(* Logix 5000 project; controller DNP3Master vendor 1 type 14 code 96 rev 19.13; software revision 19.01 *)

TASK DNP3ReportByException (periodic, rate 20 ms, priority 10, watchdog 500 ms) : DNP3Events
TASK MainTask (continuous, watchdog 500 ms) : MainProgram

MODULES
   Local : vendor 1 type 14 code 96 (ICP 0, rev 19.13)
      eth : vendor 1 type 12 code 200 (Ethernet 192.168.1.129, ICP 1, rev 5.7)
         PLX51DNP : ETHERNET-MODULE (Ethernet 192.168.1.231, rev 1.1, Output RPI 10 ms)
END_MODULES

TYPE PLX51DNPInput :
STRUCT
   Instance : STRING;
   Status : PLX51DNPStatus;
   MasterMappedStatus : BOOL[1024];
   TransactionRate : DINT;
   Temperature : REAL;
   DNP3RxPacketCount : DINT;
   DNP3TxPacketCount : DINT;
   DNP3ChecksumErrors : DINT;
   DNP3MsgTimeout : DINT;
   AuthenticationFailures : DINT;
   SessionKeyChanges : DINT;
   TagReads : DINT;
   TagWrites : DINT;
   TagConnectionFailures : DINT;
   TagErrors : DINT;
   MasterEventBufferIndex : DINT;
END_STRUCT
END_TYPE

TYPE PLX51DNPOutput :
STRUCT
   RoutingInhibited : BOOL;
END_STRUCT
END_TYPE

TYPE PLX51DNPStatus :
STRUCT
   ReactiveTagMode : BOOL;
   ScheduledTagMode : BOOL;
   UnscheduledMode : BOOL;
   ConfigurationValid : BOOL;
   RoutingInhibited : BOOL;
   DNP3EventLogOk : BOOL;
   DNP3EventLogOverflow : BOOL;
END_STRUCT
END_TYPE

TYPE PSDNP3AnalogInput16Flag :
STRUCT
   Online : BOOL;
   Restart : BOOL;
   CommLost : BOOL;
   RemoteForced : BOOL;
   LocalForced : BOOL;
   OverRange : BOOL;
   ReferenceError : BOOL;
   Value : INT;
END_STRUCT
END_TYPE

TYPE PSDNP3AnalogInput32Flag :
STRUCT
   Online : BOOL;
   Restart : BOOL;
   CommLost : BOOL;
   RemoteForced : BOOL;
   LocalForced : BOOL;
   OverRange : BOOL;
   ReferenceError : BOOL;
   Value : DINT;
END_STRUCT
END_TYPE

TYPE PSDNP3AnalogInputRealFlag :
STRUCT
   Online : BOOL;
   Restart : BOOL;
   CommLost : BOOL;
   RemoteForced : BOOL;
   LocalForced : BOOL;
   OverRange : BOOL;
   ReferenceError : BOOL;
   Value : REAL;
END_STRUCT
END_TYPE

TYPE PSDNP3AnalogInputVar0 :
STRUCT
   Online : BOOL;
   Restart : BOOL;
   CommLost : BOOL;
   RemoteForced : BOOL;
   LocalForced : BOOL;
   OverRange : BOOL;
   ReferenceError : BOOL;
   IntValue : DINT;
   FloatValue : REAL;
END_STRUCT
END_TYPE

TYPE PSDNP3AnalogOutput16 :
STRUCT
   RequestPending : BOOL;
   Reserved : INT;
   Value : INT;
   Status : SINT;
END_STRUCT
END_TYPE

TYPE PSDNP3AnalogOutput32 :
STRUCT
   RequestPending : BOOL;
   Reserved : INT;
   Value : DINT;
   Status : SINT;
END_STRUCT
END_TYPE

TYPE PSDNP3AnalogOutputReal :
STRUCT
   RequestPending : BOOL;
   Reserved : INT;
   Value : REAL;
   Status : SINT;
END_STRUCT
END_TYPE

TYPE PSDNP3AnalogOutputStatus16Flag :
STRUCT
   Online : BOOL;
   Restart : BOOL;
   CommLost : BOOL;
   RemoteForced : BOOL;
   LocalForced : BOOL;
   OverRange : BOOL;
   ReferenceError : BOOL;
   Value : INT;
END_STRUCT
END_TYPE

TYPE PSDNP3AnalogOutputStatus32Flag :
STRUCT
   Online : BOOL;
   Restart : BOOL;
   CommLost : BOOL;
   RemoteForced : BOOL;
   LocalForced : BOOL;
   OverRange : BOOL;
   ReferenceError : BOOL;
   Value : DINT;
END_STRUCT
END_TYPE

TYPE PSDNP3AnalogOutputStatusRealFlag :
STRUCT
   Online : BOOL;
   Restart : BOOL;
   CommLost : BOOL;
   RemoteForced : BOOL;
   LocalForced : BOOL;
   OverRange : BOOL;
   ReferenceError : BOOL;
   Value : REAL;
END_STRUCT
END_TYPE

TYPE PSDNP3AnalogOutputVar0 :
STRUCT
   Online : BOOL;
   Restart : BOOL;
   CommLost : BOOL;
   RemoteForced : BOOL;
   LocalForced : BOOL;
   OverRange : BOOL;
   ReferenceError : BOOL;
   IntValue : DINT;
   FloatValue : REAL;
END_STRUCT
END_TYPE

TYPE PSDNP3BinaryInputPacked :
STRUCT
   BinaryValues : SINT[32];
END_STRUCT
END_TYPE

TYPE PSDNP3BinaryInputWithFlag :
STRUCT
   Online : BOOL;
   Restart : BOOL;
   CommLost : BOOL;
   RemoteForced : BOOL;
   LocalForced : BOOL;
   ChatterFilter : BOOL;
   Reserved : BOOL;
   State : BOOL;
END_STRUCT
END_TYPE

TYPE PSDNP3BinaryOutputPacked :
STRUCT
   BinaryValues : SINT[32];
END_STRUCT
END_TYPE

TYPE PSDNP3BinaryOutputPulse :
STRUCT
   Count : SINT;
   OnTimer : TIMER;
   OffTimer : TIMER;
END_STRUCT
END_TYPE

TYPE PSDNP3BinaryOutputWithFlag :
STRUCT
   Online : BOOL;
   Restart : BOOL;
   CommLost : BOOL;
   RemoteForced : BOOL;
   LocalForced : BOOL;
   Reserved1 : BOOL;
   Reserved2 : BOOL;
   State : BOOL;
END_STRUCT
END_TYPE

TYPE PSDNP3Counter16WithFlag :
STRUCT
   Online : BOOL;
   Restart : BOOL;
   CommLost : BOOL;
   RemoteForced : BOOL;
   LocalForced : BOOL;
   RollOver : BOOL;
   Discontinuity : BOOL;
   Value : INT;
END_STRUCT
END_TYPE

TYPE PSDNP3Counter32WithFlag :
STRUCT
   Online : BOOL;
   Restart : BOOL;
   CommLost : BOOL;
   RemoteForced : BOOL;
   LocalForced : BOOL;
   RollOver : BOOL;
   Discontinuity : BOOL;
   Value : DINT;
END_STRUCT
END_TYPE

TYPE PSDNP3CROB :
STRUCT
   RequestPending : BOOL;
   Reserved : INT;
   ControlCode : SINT;
   Count : SINT;
   OnTime : DINT;
   OffTime : DINT;
   StatusCode : SINT;
END_STRUCT
END_TYPE

TYPE PSDNP3DoubleBinaryInputPacked :
STRUCT
   BinaryValues : SINT[32];
END_STRUCT
END_TYPE

TYPE PSDNP3DoubleBinaryInputWithFlag :
STRUCT
   Online : BOOL;
   Restart : BOOL;
   CommLost : BOOL;
   RemoteForced : BOOL;
   LocalForced : BOOL;
   ChatterFilter : BOOL;
   State0 : BOOL;
   State1 : BOOL;
END_STRUCT
END_TYPE

TYPE PSDNP3FreezeCmd :
STRUCT
   RequestPending : BOOL;
END_STRUCT
END_TYPE

TYPE PSDNP3FrozenAnalog16WithFlag :
STRUCT
   Online : BOOL;
   Restart : BOOL;
   CommLost : BOOL;
   RemoteForced : BOOL;
   LocalForced : BOOL;
   OverRange : BOOL;
   ReferenceErr : BOOL;
   Value : INT;
END_STRUCT
END_TYPE

TYPE PSDNP3FrozenAnalog16WithFlagTime :
STRUCT
   Online : BOOL;
   Restart : BOOL;
   CommLost : BOOL;
   RemoteForced : BOOL;
   LocalForced : BOOL;
   OverRange : BOOL;
   ReferenceErr : BOOL;
   Value : INT;
   Reserved : DINT;
   TimeOfOccurrence : LINT;
END_STRUCT
END_TYPE

TYPE PSDNP3FrozenAnalog32WithFlag :
STRUCT
   Online : BOOL;
   Restart : BOOL;
   CommLost : BOOL;
   RemoteForced : BOOL;
   LocalForced : BOOL;
   OverRange : BOOL;
   ReferenceErr : BOOL;
   Value : DINT;
END_STRUCT
END_TYPE

TYPE PSDNP3FrozenAnalog32WithFlagTime :
STRUCT
   Online : BOOL;
   Restart : BOOL;
   CommLost : BOOL;
   RemoteForced : BOOL;
   LocalForced : BOOL;
   OverRange : BOOL;
   ReferenceErr : BOOL;
   Value : DINT;
   TimeOfOccurrence : LINT;
END_STRUCT
END_TYPE

TYPE PSDNP3FrozenAnalogRealWithFlag :
STRUCT
   Online : BOOL;
   Restart : BOOL;
   CommLost : BOOL;
   RemoteForced : BOOL;
   LocalForced : BOOL;
   OverRange : BOOL;
   ReferenceErr : BOOL;
   Value : REAL;
END_STRUCT
END_TYPE

TYPE PSDNP3FrozenCounter16WithFlag :
STRUCT
   Online : BOOL;
   Restart : BOOL;
   CommLost : BOOL;
   RemoteForced : BOOL;
   LocalForced : BOOL;
   RollOver : BOOL;
   Discontinuity : BOOL;
   Value : INT;
END_STRUCT
END_TYPE

TYPE PSDNP3FrozenCounter16WithFlagTime :
STRUCT
   Online : BOOL;
   Restart : BOOL;
   CommLost : BOOL;
   RemoteForced : BOOL;
   LocalForced : BOOL;
   RollOver : BOOL;
   Discontinuity : BOOL;
   Value : INT;
   TimeOfOccurrence : LINT;
END_STRUCT
END_TYPE

TYPE PSDNP3FrozenCounter32WithFlag :
STRUCT
   Online : BOOL;
   Restart : BOOL;
   CommLost : BOOL;
   RemoteForced : BOOL;
   LocalForced : BOOL;
   RollOver : BOOL;
   Discontinuity : BOOL;
   Value : DINT;
END_STRUCT
END_TYPE

TYPE PSDNP3FrozenCounter32WithFlagTime :
STRUCT
   Online : BOOL;
   Restart : BOOL;
   CommLost : BOOL;
   RemoteForced : BOOL;
   LocalForced : BOOL;
   RollOver : BOOL;
   Discontinuity : BOOL;
   Value : DINT;
   TimeOfOccurrence : LINT;
END_STRUCT
END_TYPE

TYPE PSDNP3MasterEvent :
STRUCT
   EvtPending : DINT;
   EvtGroup : SINT;
   EvtFlags : SINT;
   EvtSrcNodeAddress : INT;
   EvtSrcIPAddress : INT[4];
   EvtElementIndex : DINT;
   Reserved : DINT;
   EvtTimeStamp : LINT;
   EvtFloatValue : REAL;
   EvtIntegerValue : DINT;
END_STRUCT
END_TYPE

TYPE PSDNP3MsgRequest :
STRUCT
   DestinationNode : INT;
   RequestDataSize : INT;
   IPAddress : INT[4];
   Function : DINT;
   RequestData : SINT[255];
END_STRUCT
END_TYPE

TYPE PSDNP3MsgResponse :
STRUCT
   DNP3Indicators : INT;
   ResponseDataSize : INT;
   ResponseData : SINT[255];
END_STRUCT
END_TYPE

ADD_ON_INSTRUCTION PSDNP3EventG01V02   (* revision 1.0, vendor ProSoft Technology Inc *)
// Processes DNP3 Event and updates corresponding static DNP3 object. (Report by Exception.)
// G01V02 - Binary Input - with Status
VAR_IN_OUT
   EventBuffer : PSDNP3MasterEvent[1]; {required}
END_VAR
VAR_INPUT
   BufferSize : DINT; {required}
   CurrentBufferIndex : DINT; {required}
   Reset : BOOL; {required}
   OutstationNodeAddress : INT; {required}
   OutstationIPAddress0 : INT; {required}
   OutstationIPAddress1 : INT; {required}
   OutstationIPAddress2 : INT; {required}
   OutstationIPAddress3 : INT; {required}
END_VAR
VAR_IN_OUT
   DNP3StaticObject : PSDNP3BinaryInputWithFlag[1]; {required}
END_VAR
VAR_INPUT
   MaxtElementCount : DINT; {required}
END_VAR
VAR_OUTPUT
   EventsProcessed : DINT; {access Read Only, visible}
   LastElementIndex : DINT; {access Read Only, visible}
   LastValue : BOOL; {access Read Only, visible}
   LastStatus : SINT; {access Read Only, visible}
   CurrentUnloadIndex : DINT; {access Read Only, visible}
END_VAR
VAR
   UnloadIndex : DINT; {access None}
   EnableInTemp : BOOL; {access None}
   InitialScan : BOOL; {access None}
   EntryValidForProcessing : BOOL; {access None}
   ElementIndex : DINT; {access None}
   NextIndex : DINT; {access None}
   ResetPulse : BOOL; {access None}
   ResetONS : BOOL; {access None}
END_VAR

ROUTINE Logic   (* ladder *)
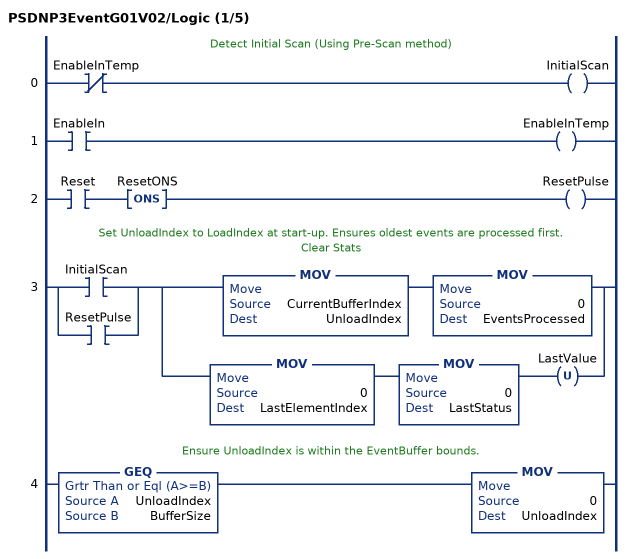
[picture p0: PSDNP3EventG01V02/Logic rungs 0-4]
   // Detect Initial Scan (Using Pre-Scan method)
   0: XIO(EnableInTemp)OTE(InitialScan);
   1: XIC(EnableIn)OTE(EnableInTemp);
   2: XIC(Reset)ONS(ResetONS)OTE(ResetPulse);
   // Set UnloadIndex to LoadIndex at start-up. Ensures oldest events are processed first.
   // Clear Stats
   3: [XIC(InitialScan) ,XIC(ResetPulse) ][MOV(CurrentBufferIndex,UnloadIndex) MOV(0,EventsProcessed) ,MOV(0,LastElementIndex) MOV(0,LastStatus) OTU(LastValue) ];
   // Ensure UnloadIndex is within the EventBuffer bounds.
   4: GEQ(UnloadIndex,BufferSize)MOV(0,UnloadIndex);
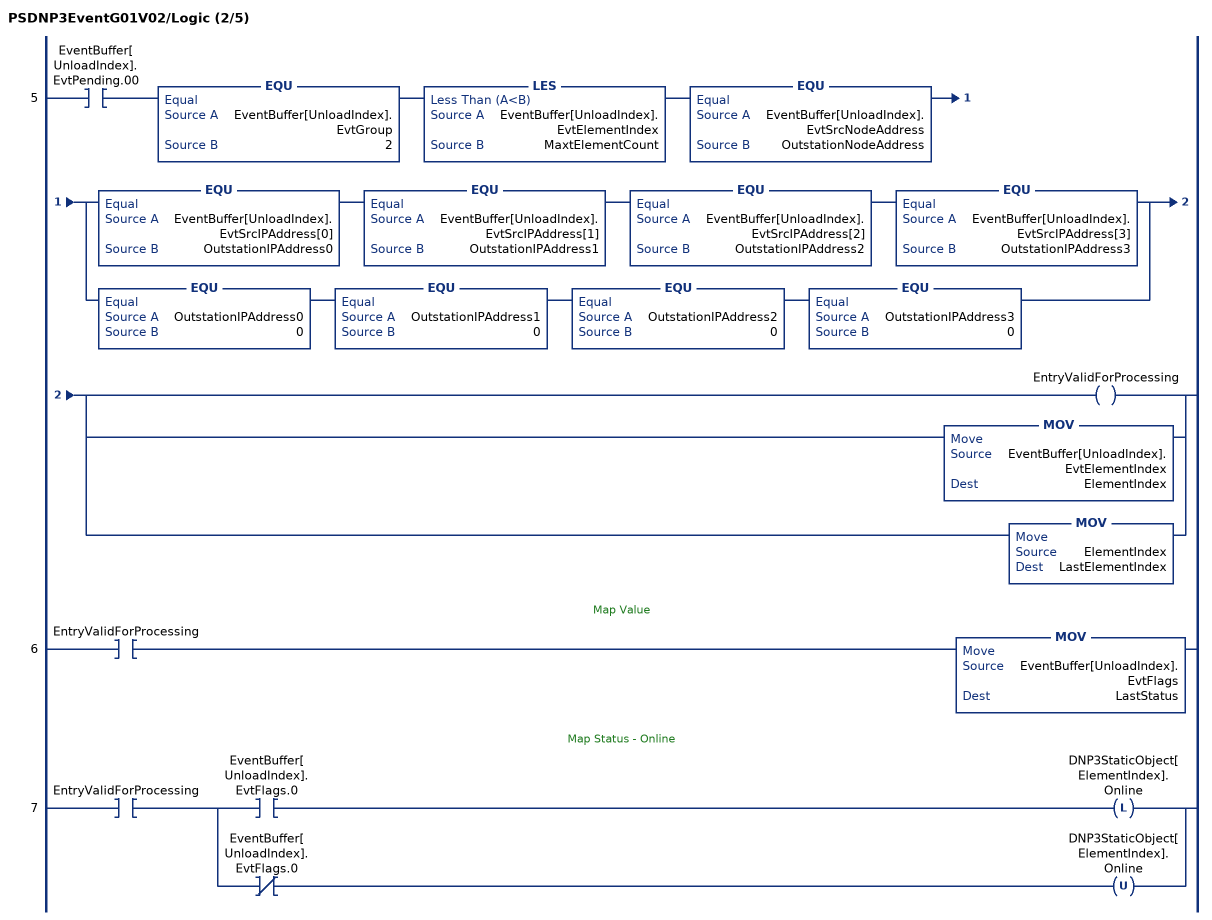
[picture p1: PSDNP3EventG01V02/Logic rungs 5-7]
   5: XIC(EventBuffer[UnloadIndex].EvtPending.00)EQU(EventBuffer[UnloadIndex].EvtGroup,2)LES(EventBuffer[UnloadIndex].EvtElementIndex,MaxtElementCount)EQU(EventBuffer[UnloadIndex].EvtSrcNodeAddress,OutstationNodeAddress)[EQU(EventBuffer[UnloadIndex].EvtSrcIPAddress[0],OutstationIPAddress0) EQU(EventBuffer[UnloadIndex].EvtSrcIPAddress[1],OutstationIPAddress1) EQU(EventBuffer[UnloadIndex].EvtSrcIPAddress[2],OutstationIPAddress2) EQU(EventBuffer[UnloadIndex].EvtSrcIPAddress[3],OutstationIPAddress3) ,EQU(OutstationIPAddress0,0) EQU(OutstationIPAddress1,0) EQU(OutstationIPAddress2,0) EQU(OutstationIPAddress3,0) ][OTE(EntryValidForProcessing) ,MOV(EventBuffer[UnloadIndex].EvtElementIndex,ElementIndex) ,MOV(ElementIndex,LastElementIndex) ];
   // Map Value
   6: XIC(EntryValidForProcessing)MOV(EventBuffer[UnloadIndex].EvtFlags,LastStatus);
   // Map Status - Online
   7: XIC(EntryValidForProcessing)[XIC(EventBuffer[UnloadIndex].EvtFlags.0) OTL(DNP3StaticObject[ElementIndex].Online) ,XIO(EventBuffer[UnloadIndex].EvtFlags.0) OTU(DNP3StaticObject[ElementIndex].Online) ];
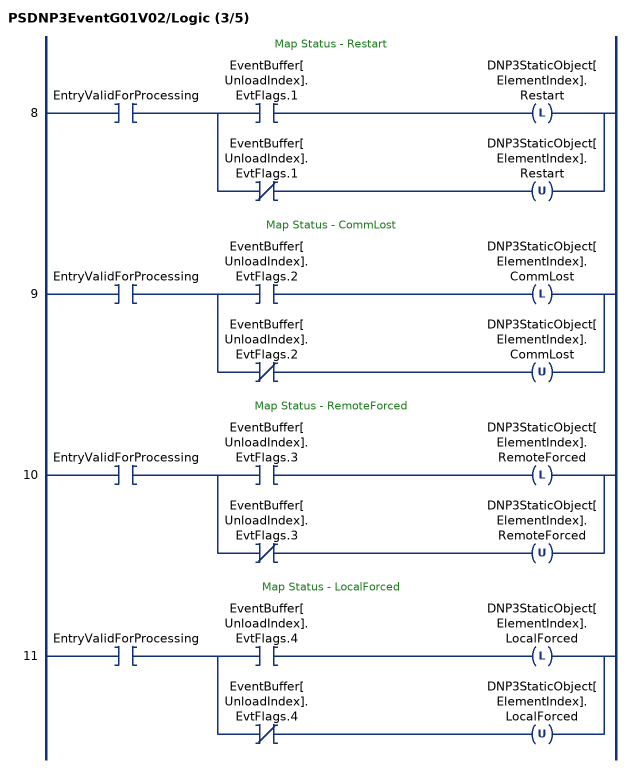
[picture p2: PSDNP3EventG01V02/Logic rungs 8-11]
   // Map Status - Restart
   8: XIC(EntryValidForProcessing)[XIC(EventBuffer[UnloadIndex].EvtFlags.1) OTL(DNP3StaticObject[ElementIndex].Restart) ,XIO(EventBuffer[UnloadIndex].EvtFlags.1) OTU(DNP3StaticObject[ElementIndex].Restart) ];
   // Map Status - CommLost
   9: XIC(EntryValidForProcessing)[XIC(EventBuffer[UnloadIndex].EvtFlags.2) OTL(DNP3StaticObject[ElementIndex].CommLost) ,XIO(EventBuffer[UnloadIndex].EvtFlags.2) OTU(DNP3StaticObject[ElementIndex].CommLost) ];
   // Map Status - RemoteForced
   10: XIC(EntryValidForProcessing)[XIC(EventBuffer[UnloadIndex].EvtFlags.3) OTL(DNP3StaticObject[ElementIndex].RemoteForced) ,XIO(EventBuffer[UnloadIndex].EvtFlags.3) OTU(DNP3StaticObject[ElementIndex].RemoteForced) ];
   // Map Status - LocalForced
   11: XIC(EntryValidForProcessing)[XIC(EventBuffer[UnloadIndex].EvtFlags.4) OTL(DNP3StaticObject[ElementIndex].LocalForced) ,XIO(EventBuffer[UnloadIndex].EvtFlags.4) OTU(DNP3StaticObject[ElementIndex].LocalForced) ];
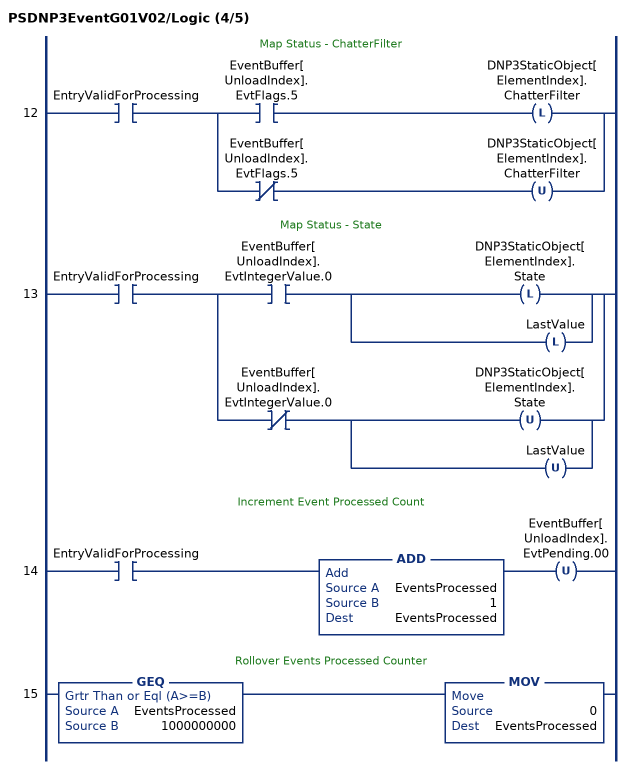
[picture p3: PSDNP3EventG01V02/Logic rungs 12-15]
   // Map Status - ChatterFilter
   12: XIC(EntryValidForProcessing)[XIC(EventBuffer[UnloadIndex].EvtFlags.5) OTL(DNP3StaticObject[ElementIndex].ChatterFilter) ,XIO(EventBuffer[UnloadIndex].EvtFlags.5) OTU(DNP3StaticObject[ElementIndex].ChatterFilter) ];
   // Map Status - State
   13: XIC(EntryValidForProcessing)[XIC(EventBuffer[UnloadIndex].EvtIntegerValue.0) [OTL(DNP3StaticObject[ElementIndex].State) ,OTL(LastValue) ] ,XIO(EventBuffer[UnloadIndex].EvtIntegerValue.0) [OTU(DNP3StaticObject[ElementIndex].State) ,OTU(LastValue) ] ];
   // Increment Event Processed Count
   14: XIC(EntryValidForProcessing)ADD(EventsProcessed,1,EventsProcessed)OTU(EventBuffer[UnloadIndex].EvtPending.00);
   // Rollover Events Processed Counter
   15: GEQ(EventsProcessed,1000000000)MOV(0,EventsProcessed);
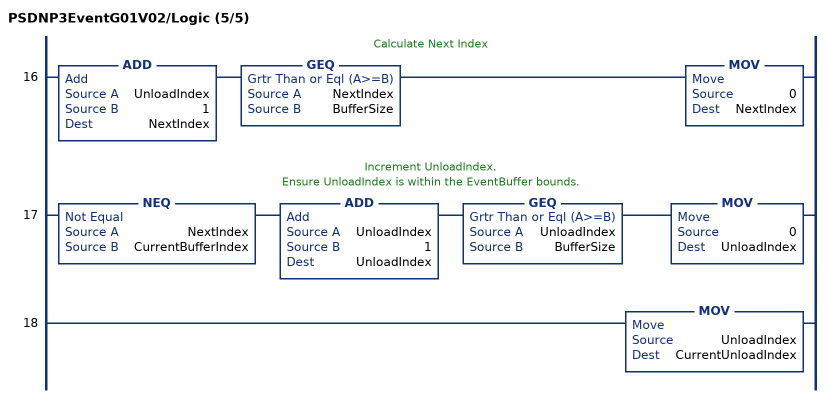
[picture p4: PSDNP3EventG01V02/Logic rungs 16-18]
   // Calculate Next Index
   16: ADD(UnloadIndex,1,NextIndex)GEQ(NextIndex,BufferSize)MOV(0,NextIndex);
   // Increment UnloadIndex.
   // Ensure UnloadIndex is within the EventBuffer bounds.
   17: NEQ(NextIndex,CurrentBufferIndex)ADD(UnloadIndex,1,UnloadIndex)GEQ(UnloadIndex,BufferSize)MOV(0,UnloadIndex);
   18: MOV(UnloadIndex,CurrentUnloadIndex);
END_ROUTINE
END_ADD_ON_INSTRUCTION

ADD_ON_INSTRUCTION PSDNP3EventG03V02   (* revision 1.0, vendor ProSoft Technology Inc *)
// Processes DNP3 Event and updates corresponding static DNP3 object. (Report by Exception.)
// G03V02 - Double Binary Input - with Status
VAR_IN_OUT
   EventBuffer : PSDNP3MasterEvent[1]; {required}
END_VAR
VAR_INPUT
   BufferSize : DINT; {required}
   CurrentBufferIndex : DINT; {required}
   Reset : BOOL; {required}
   OutstationNodeAddress : INT; {required}
   OutstationIPAddress0 : INT; {required}
   OutstationIPAddress1 : INT; {required}
   OutstationIPAddress2 : INT; {required}
   OutstationIPAddress3 : INT; {required}
END_VAR
VAR_IN_OUT
   DNP3StaticObject : PSDNP3DoubleBinaryInputWithFlag[1]; {required}
END_VAR
VAR_INPUT
   MaxtElementCount : DINT; {required}
END_VAR
VAR_OUTPUT
   EventsProcessed : DINT; {access Read Only, visible}
   LastElementIndex : DINT; {access Read Only, visible}
   LastValue : SINT; {access Read Only, visible}
   LastStatus : SINT; {access Read Only, visible}
   CurrentUnloadIndex : DINT; {access Read Only, visible}
END_VAR
VAR
   UnloadIndex : DINT; {access None}
   EnableInTemp : BOOL; {access None}
   InitialScan : BOOL; {access None}
   EntryValidForProcessing : BOOL; {access None}
   ElementIndex : DINT; {access None}
   NextIndex : DINT; {access None}
   ResetPulse : BOOL; {access None}
   ResetONS : BOOL; {access None}
END_VAR

ROUTINE Logic   (* ladder *)
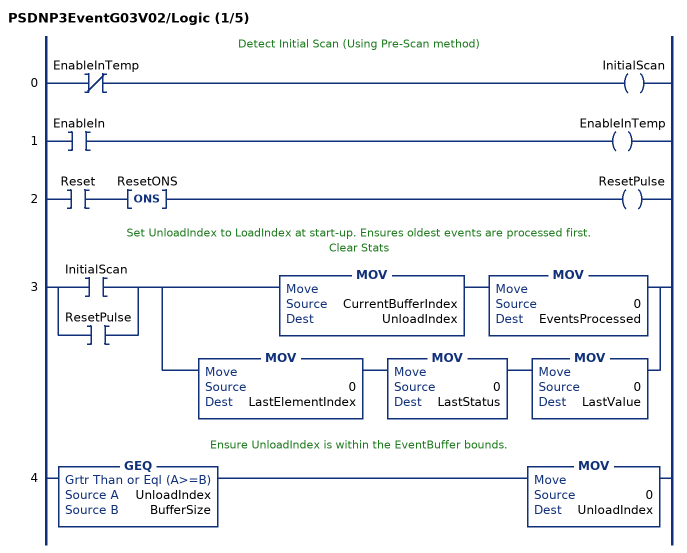
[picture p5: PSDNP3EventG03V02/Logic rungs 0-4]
   // Detect Initial Scan (Using Pre-Scan method)
   0: XIO(EnableInTemp)OTE(InitialScan);
   1: XIC(EnableIn)OTE(EnableInTemp);
   2: XIC(Reset)ONS(ResetONS)OTE(ResetPulse);
   // Set UnloadIndex to LoadIndex at start-up. Ensures oldest events are processed first.
   // Clear Stats
   3: [XIC(InitialScan) ,XIC(ResetPulse) ][MOV(CurrentBufferIndex,UnloadIndex) MOV(0,EventsProcessed) ,MOV(0,LastElementIndex) MOV(0,LastStatus) MOV(0,LastValue) ];
   // Ensure UnloadIndex is within the EventBuffer bounds.
   4: GEQ(UnloadIndex,BufferSize)MOV(0,UnloadIndex);
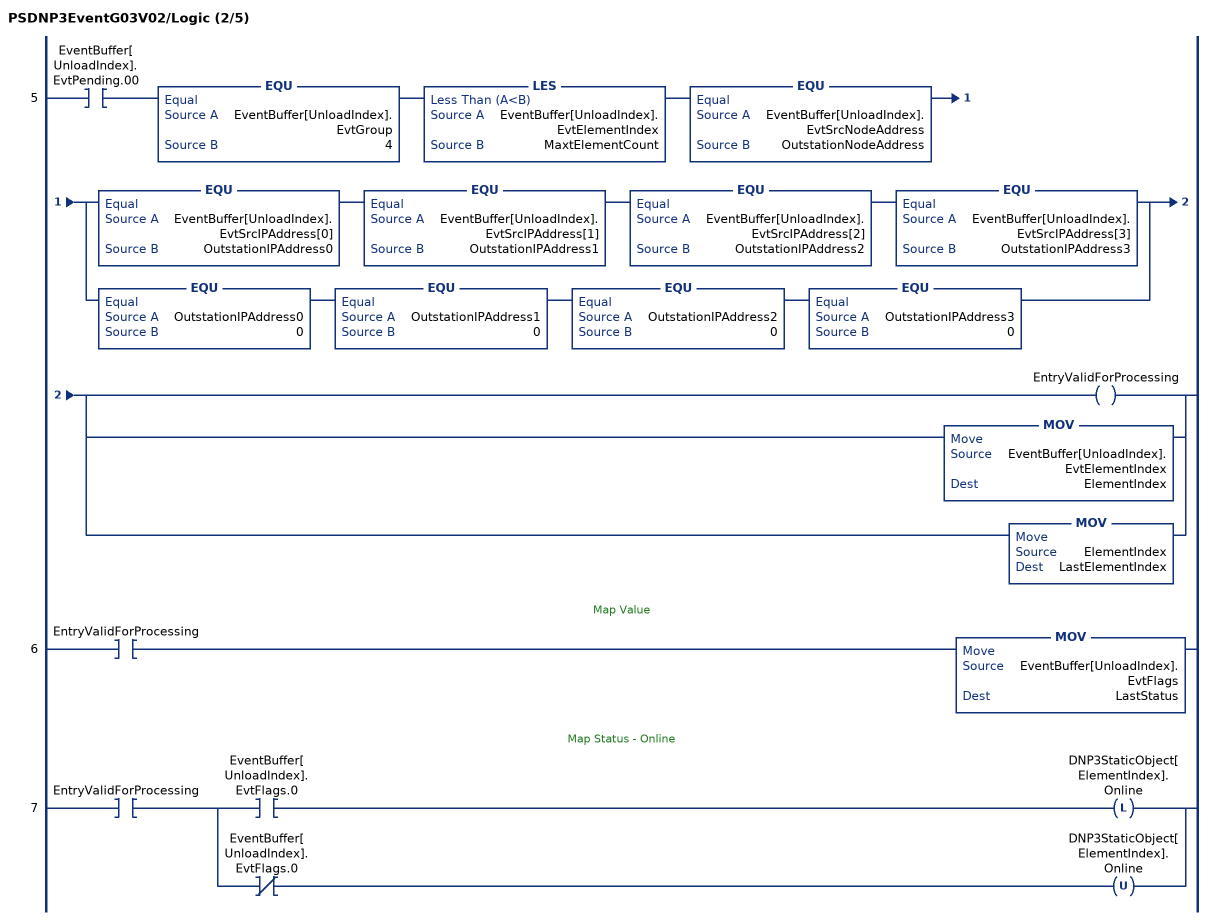
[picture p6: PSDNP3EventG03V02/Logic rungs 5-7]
   5: XIC(EventBuffer[UnloadIndex].EvtPending.00)EQU(EventBuffer[UnloadIndex].EvtGroup,4)LES(EventBuffer[UnloadIndex].EvtElementIndex,MaxtElementCount)EQU(EventBuffer[UnloadIndex].EvtSrcNodeAddress,OutstationNodeAddress)[EQU(EventBuffer[UnloadIndex].EvtSrcIPAddress[0],OutstationIPAddress0) EQU(EventBuffer[UnloadIndex].EvtSrcIPAddress[1],OutstationIPAddress1) EQU(EventBuffer[UnloadIndex].EvtSrcIPAddress[2],OutstationIPAddress2) EQU(EventBuffer[UnloadIndex].EvtSrcIPAddress[3],OutstationIPAddress3) ,EQU(OutstationIPAddress0,0) EQU(OutstationIPAddress1,0) EQU(OutstationIPAddress2,0) EQU(OutstationIPAddress3,0) ][OTE(EntryValidForProcessing) ,MOV(EventBuffer[UnloadIndex].EvtElementIndex,ElementIndex) ,MOV(ElementIndex,LastElementIndex) ];
   // Map Value
   6: XIC(EntryValidForProcessing)MOV(EventBuffer[UnloadIndex].EvtFlags,LastStatus);
   // Map Status - Online
   7: XIC(EntryValidForProcessing)[XIC(EventBuffer[UnloadIndex].EvtFlags.0) OTL(DNP3StaticObject[ElementIndex].Online) ,XIO(EventBuffer[UnloadIndex].EvtFlags.0) OTU(DNP3StaticObject[ElementIndex].Online) ];
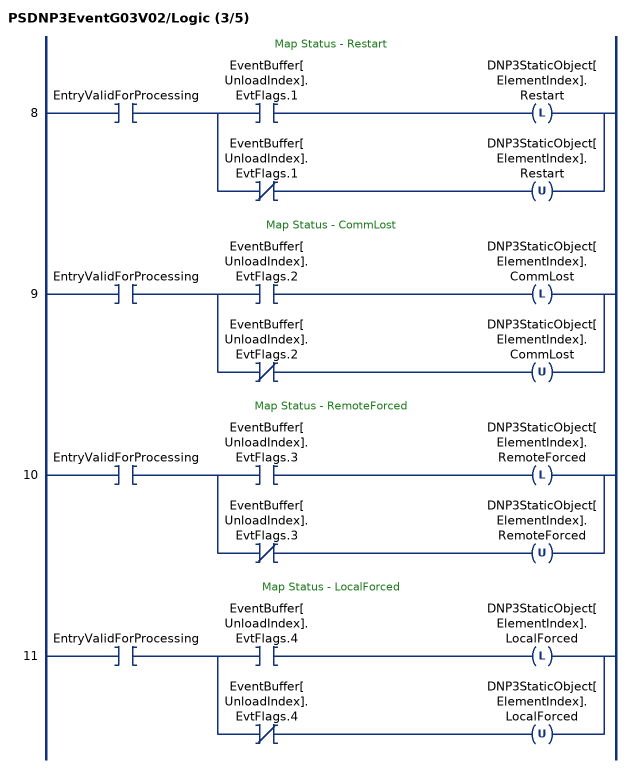
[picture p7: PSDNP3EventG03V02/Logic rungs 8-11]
   // Map Status - Restart
   8: XIC(EntryValidForProcessing)[XIC(EventBuffer[UnloadIndex].EvtFlags.1) OTL(DNP3StaticObject[ElementIndex].Restart) ,XIO(EventBuffer[UnloadIndex].EvtFlags.1) OTU(DNP3StaticObject[ElementIndex].Restart) ];
   // Map Status - CommLost
   9: XIC(EntryValidForProcessing)[XIC(EventBuffer[UnloadIndex].EvtFlags.2) OTL(DNP3StaticObject[ElementIndex].CommLost) ,XIO(EventBuffer[UnloadIndex].EvtFlags.2) OTU(DNP3StaticObject[ElementIndex].CommLost) ];
   // Map Status - RemoteForced
   10: XIC(EntryValidForProcessing)[XIC(EventBuffer[UnloadIndex].EvtFlags.3) OTL(DNP3StaticObject[ElementIndex].RemoteForced) ,XIO(EventBuffer[UnloadIndex].EvtFlags.3) OTU(DNP3StaticObject[ElementIndex].RemoteForced) ];
   // Map Status - LocalForced
   11: XIC(EntryValidForProcessing)[XIC(EventBuffer[UnloadIndex].EvtFlags.4) OTL(DNP3StaticObject[ElementIndex].LocalForced) ,XIO(EventBuffer[UnloadIndex].EvtFlags.4) OTU(DNP3StaticObject[ElementIndex].LocalForced) ];
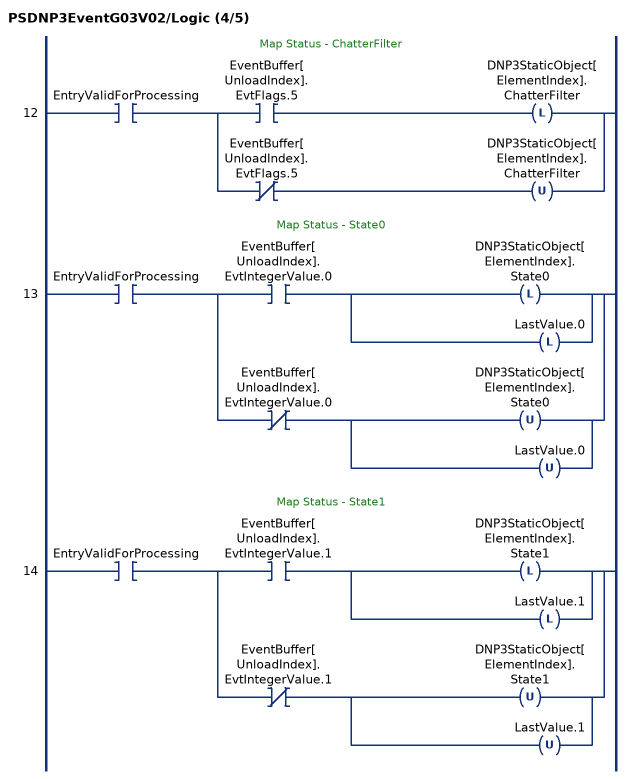
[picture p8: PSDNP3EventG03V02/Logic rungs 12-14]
   // Map Status - ChatterFilter
   12: XIC(EntryValidForProcessing)[XIC(EventBuffer[UnloadIndex].EvtFlags.5) OTL(DNP3StaticObject[ElementIndex].ChatterFilter) ,XIO(EventBuffer[UnloadIndex].EvtFlags.5) OTU(DNP3StaticObject[ElementIndex].ChatterFilter) ];
   // Map Status - State0
   13: XIC(EntryValidForProcessing)[XIC(EventBuffer[UnloadIndex].EvtIntegerValue.0) [OTL(DNP3StaticObject[ElementIndex].State0) ,OTL(LastValue.0) ] ,XIO(EventBuffer[UnloadIndex].EvtIntegerValue.0) [OTU(DNP3StaticObject[ElementIndex].State0) ,OTU(LastValue.0) ] ];
   // Map Status - State1
   14: XIC(EntryValidForProcessing)[XIC(EventBuffer[UnloadIndex].EvtIntegerValue.1) [OTL(DNP3StaticObject[ElementIndex].State1) ,OTL(LastValue.1) ] ,XIO(EventBuffer[UnloadIndex].EvtIntegerValue.1) [OTU(DNP3StaticObject[ElementIndex].State1) ,OTU(LastValue.1) ] ];
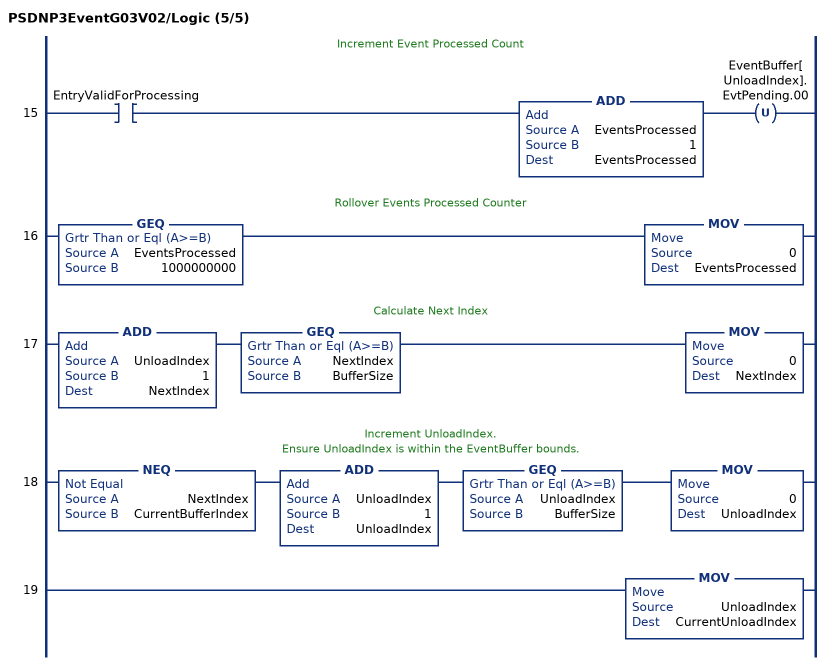
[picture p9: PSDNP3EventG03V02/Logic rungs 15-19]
   // Increment Event Processed Count
   15: XIC(EntryValidForProcessing)ADD(EventsProcessed,1,EventsProcessed)OTU(EventBuffer[UnloadIndex].EvtPending.00);
   // Rollover Events Processed Counter
   16: GEQ(EventsProcessed,1000000000)MOV(0,EventsProcessed);
   // Calculate Next Index
   17: ADD(UnloadIndex,1,NextIndex)GEQ(NextIndex,BufferSize)MOV(0,NextIndex);
   // Increment UnloadIndex.
   // Ensure UnloadIndex is within the EventBuffer bounds.
   18: NEQ(NextIndex,CurrentBufferIndex)ADD(UnloadIndex,1,UnloadIndex)GEQ(UnloadIndex,BufferSize)MOV(0,UnloadIndex);
   19: MOV(UnloadIndex,CurrentUnloadIndex);
END_ROUTINE
END_ADD_ON_INSTRUCTION

ADD_ON_INSTRUCTION PSDNP3EventG10V02   (* revision 1.0, vendor ProSoft Technology Inc *)
// Processes DNP3 Event and updates corresponding static DNP3 object. (Report by Exception.)
// G10V02 - Binary Ouput - with Status
VAR_IN_OUT
   EventBuffer : PSDNP3MasterEvent[1]; {required}
END_VAR
VAR_INPUT
   BufferSize : DINT; {required}
   CurrentBufferIndex : DINT; {required}
   Reset : BOOL; {required}
   OutstationNodeAddress : INT; {required}
   OutstationIPAddress0 : INT; {required}
   OutstationIPAddress1 : INT; {required}
   OutstationIPAddress2 : INT; {required}
   OutstationIPAddress3 : INT; {required}
END_VAR
VAR_IN_OUT
   DNP3StaticObject : PSDNP3BinaryOutputWithFlag[1]; {required}
END_VAR
VAR_INPUT
   MaxtElementCount : DINT; {required}
END_VAR
VAR_OUTPUT
   EventsProcessed : DINT; {access Read Only, visible}
   LastElementIndex : DINT; {access Read Only, visible}
   LastValue : BOOL; {access Read Only, visible}
   LastStatus : SINT; {access Read Only, visible}
   CurrentUnloadIndex : DINT; {access Read Only, visible}
END_VAR
VAR
   UnloadIndex : DINT; {access None}
   EnableInTemp : BOOL; {access None}
   InitialScan : BOOL; {access None}
   EntryValidForProcessing : BOOL; {access None}
   ElementIndex : DINT; {access None}
   NextIndex : DINT; {access None}
   ResetPulse : BOOL; {access None}
   ResetONS : BOOL; {access None}
END_VAR

ROUTINE Logic   (* ladder *)
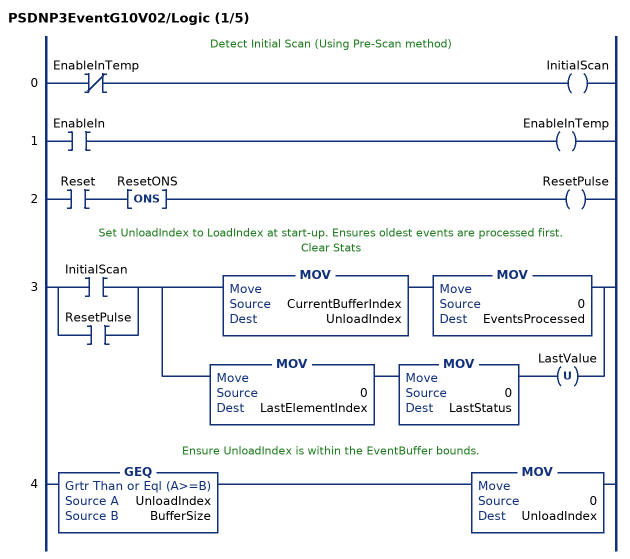
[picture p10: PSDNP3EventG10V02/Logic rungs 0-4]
   // Detect Initial Scan (Using Pre-Scan method)
   0: XIO(EnableInTemp)OTE(InitialScan);
   1: XIC(EnableIn)OTE(EnableInTemp);
   2: XIC(Reset)ONS(ResetONS)OTE(ResetPulse);
   // Set UnloadIndex to LoadIndex at start-up. Ensures oldest events are processed first.
   // Clear Stats
   3: [XIC(InitialScan) ,XIC(ResetPulse) ][MOV(CurrentBufferIndex,UnloadIndex) MOV(0,EventsProcessed) ,MOV(0,LastElementIndex) MOV(0,LastStatus) OTU(LastValue) ];
   // Ensure UnloadIndex is within the EventBuffer bounds.
   4: GEQ(UnloadIndex,BufferSize)MOV(0,UnloadIndex);
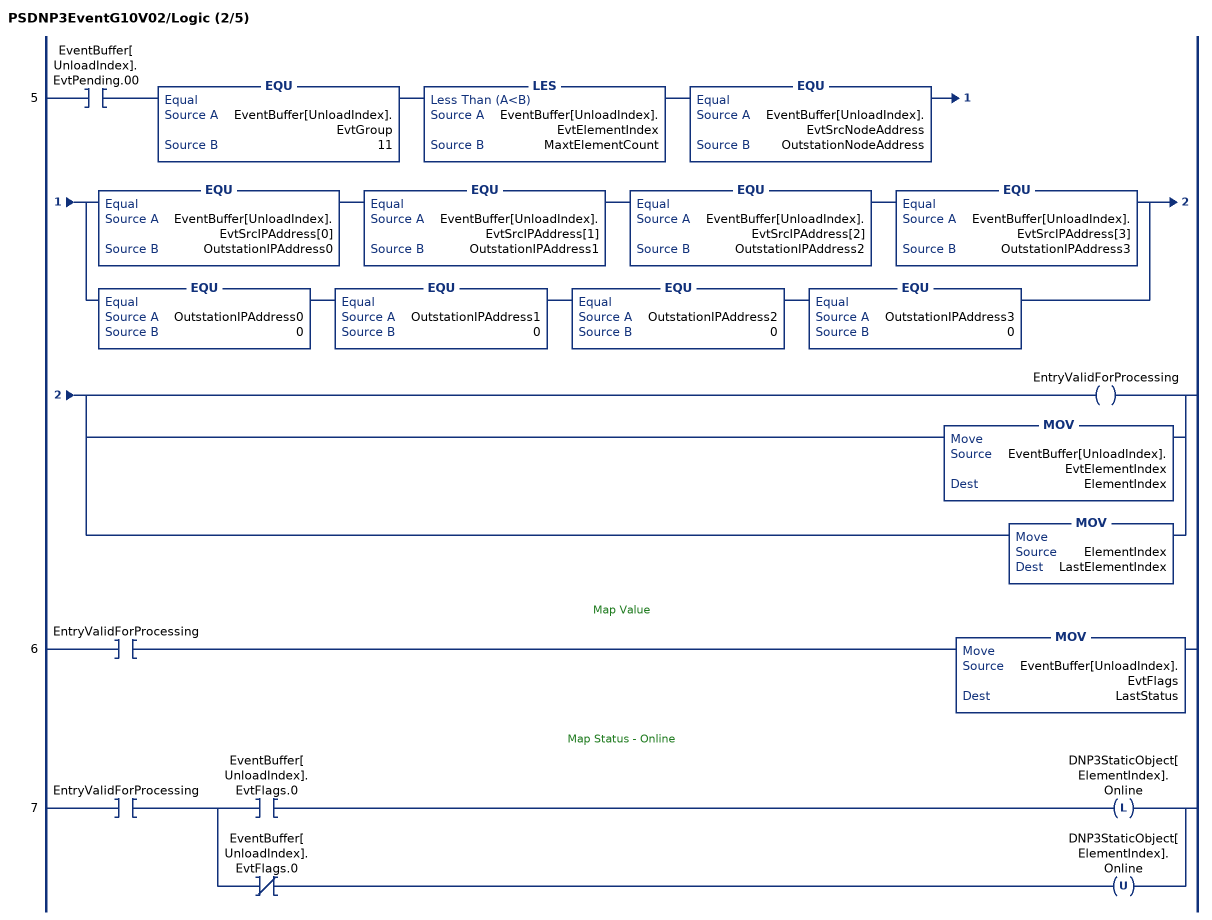
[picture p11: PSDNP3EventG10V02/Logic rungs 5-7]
   5: XIC(EventBuffer[UnloadIndex].EvtPending.00)EQU(EventBuffer[UnloadIndex].EvtGroup,11)LES(EventBuffer[UnloadIndex].EvtElementIndex,MaxtElementCount)EQU(EventBuffer[UnloadIndex].EvtSrcNodeAddress,OutstationNodeAddress)[EQU(EventBuffer[UnloadIndex].EvtSrcIPAddress[0],OutstationIPAddress0) EQU(EventBuffer[UnloadIndex].EvtSrcIPAddress[1],OutstationIPAddress1) EQU(EventBuffer[UnloadIndex].EvtSrcIPAddress[2],OutstationIPAddress2) EQU(EventBuffer[UnloadIndex].EvtSrcIPAddress[3],OutstationIPAddress3) ,EQU(OutstationIPAddress0,0) EQU(OutstationIPAddress1,0) EQU(OutstationIPAddress2,0) EQU(OutstationIPAddress3,0) ][OTE(EntryValidForProcessing) ,MOV(EventBuffer[UnloadIndex].EvtElementIndex,ElementIndex) ,MOV(ElementIndex,LastElementIndex) ];
   // Map Value
   6: XIC(EntryValidForProcessing)MOV(EventBuffer[UnloadIndex].EvtFlags,LastStatus);
   // Map Status - Online
   7: XIC(EntryValidForProcessing)[XIC(EventBuffer[UnloadIndex].EvtFlags.0) OTL(DNP3StaticObject[ElementIndex].Online) ,XIO(EventBuffer[UnloadIndex].EvtFlags.0) OTU(DNP3StaticObject[ElementIndex].Online) ];
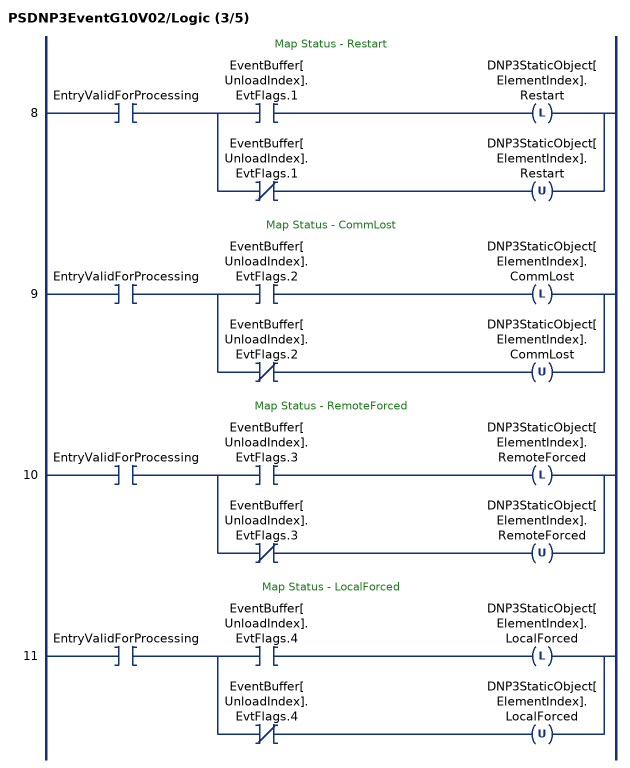
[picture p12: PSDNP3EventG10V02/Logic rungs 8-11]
   // Map Status - Restart
   8: XIC(EntryValidForProcessing)[XIC(EventBuffer[UnloadIndex].EvtFlags.1) OTL(DNP3StaticObject[ElementIndex].Restart) ,XIO(EventBuffer[UnloadIndex].EvtFlags.1) OTU(DNP3StaticObject[ElementIndex].Restart) ];
   // Map Status - CommLost
   9: XIC(EntryValidForProcessing)[XIC(EventBuffer[UnloadIndex].EvtFlags.2) OTL(DNP3StaticObject[ElementIndex].CommLost) ,XIO(EventBuffer[UnloadIndex].EvtFlags.2) OTU(DNP3StaticObject[ElementIndex].CommLost) ];
   // Map Status - RemoteForced
   10: XIC(EntryValidForProcessing)[XIC(EventBuffer[UnloadIndex].EvtFlags.3) OTL(DNP3StaticObject[ElementIndex].RemoteForced) ,XIO(EventBuffer[UnloadIndex].EvtFlags.3) OTU(DNP3StaticObject[ElementIndex].RemoteForced) ];
   // Map Status - LocalForced
   11: XIC(EntryValidForProcessing)[XIC(EventBuffer[UnloadIndex].EvtFlags.4) OTL(DNP3StaticObject[ElementIndex].LocalForced) ,XIO(EventBuffer[UnloadIndex].EvtFlags.4) OTU(DNP3StaticObject[ElementIndex].LocalForced) ];
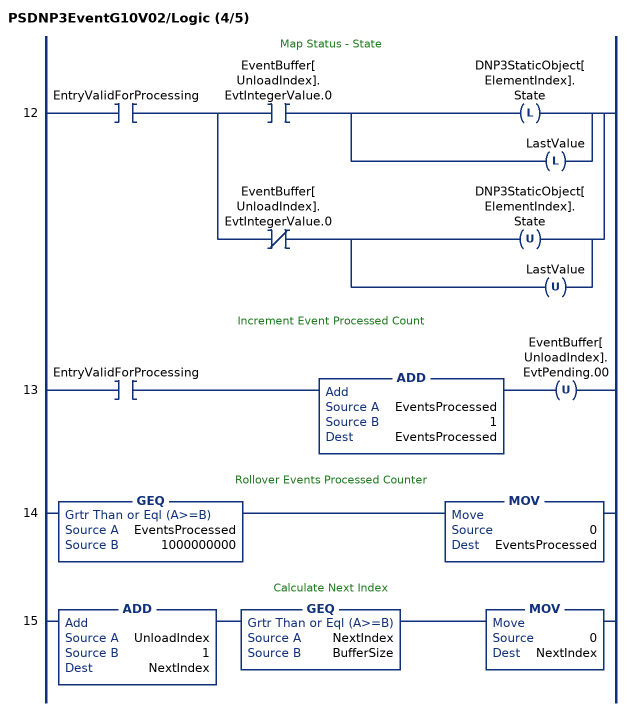
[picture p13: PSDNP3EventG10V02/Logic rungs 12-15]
   // Map Status - State
   12: XIC(EntryValidForProcessing)[XIC(EventBuffer[UnloadIndex].EvtIntegerValue.0) [OTL(DNP3StaticObject[ElementIndex].State) ,OTL(LastValue) ] ,XIO(EventBuffer[UnloadIndex].EvtIntegerValue.0) [OTU(DNP3StaticObject[ElementIndex].State) ,OTU(LastValue) ] ];
   // Increment Event Processed Count
   13: XIC(EntryValidForProcessing)ADD(EventsProcessed,1,EventsProcessed)OTU(EventBuffer[UnloadIndex].EvtPending.00);
   // Rollover Events Processed Counter
   14: GEQ(EventsProcessed,1000000000)MOV(0,EventsProcessed);
   // Calculate Next Index
   15: ADD(UnloadIndex,1,NextIndex)GEQ(NextIndex,BufferSize)MOV(0,NextIndex);
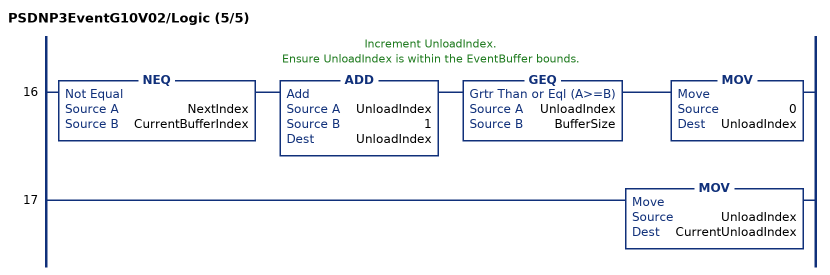
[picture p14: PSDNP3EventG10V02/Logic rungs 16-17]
   // Increment UnloadIndex.
   // Ensure UnloadIndex is within the EventBuffer bounds.
   16: NEQ(NextIndex,CurrentBufferIndex)ADD(UnloadIndex,1,UnloadIndex)GEQ(UnloadIndex,BufferSize)MOV(0,UnloadIndex);
   17: MOV(UnloadIndex,CurrentUnloadIndex);
END_ROUTINE
END_ADD_ON_INSTRUCTION

ADD_ON_INSTRUCTION PSDNP3EventG20V01   (* revision 1.0, vendor ProSoft Technology Inc *)
// Processes DNP3 Event and updates corresponding static DNP3 object. (Report by Exception.)
// G20V01 - Counter - 32bit with Status
VAR_IN_OUT
   EventBuffer : PSDNP3MasterEvent[1]; {required}
END_VAR
VAR_INPUT
   BufferSize : DINT; {required}
   CurrentBufferIndex : DINT; {required}
   Reset : BOOL; {required}
   OutstationNodeAddress : INT; {required}
   OutstationIPAddress0 : INT; {required}
   OutstationIPAddress1 : INT; {required}
   OutstationIPAddress2 : INT; {required}
   OutstationIPAddress3 : INT; {required}
END_VAR
VAR_IN_OUT
   DNP3StaticObject : PSDNP3Counter32WithFlag[1]; {required}
END_VAR
VAR_INPUT
   MaxtElementCount : DINT; {required}
END_VAR
VAR_OUTPUT
   EventsProcessed : DINT; {access Read Only, visible}
   LastElementIndex : DINT; {access Read Only, visible}
   LastValue : DINT; {access Read Only, visible}
   LastStatus : SINT; {access Read Only, visible}
   CurrentUnloadIndex : DINT; {access Read Only, visible}
END_VAR
VAR
   UnloadIndex : DINT; {access None}
   EnableInTemp : BOOL; {access None}
   InitialScan : BOOL; {access None}
   EntryValidForProcessing : BOOL; {access None}
   ElementIndex : DINT; {access None}
   NextIndex : DINT; {access None}
   ResetPulse : BOOL; {access None}
   ResetONS : BOOL; {access None}
END_VAR

ROUTINE Logic   (* ladder *)
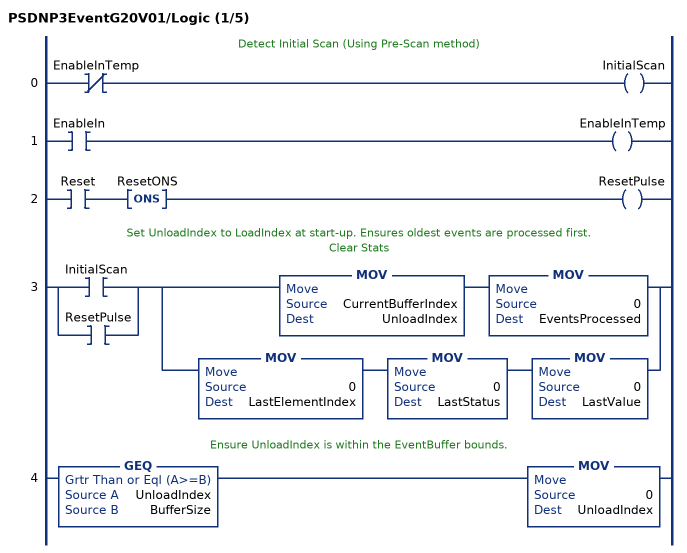
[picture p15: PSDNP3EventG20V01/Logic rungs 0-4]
   // Detect Initial Scan (Using Pre-Scan method)
   0: XIO(EnableInTemp)OTE(InitialScan);
   1: XIC(EnableIn)OTE(EnableInTemp);
   2: XIC(Reset)ONS(ResetONS)OTE(ResetPulse);
   // Set UnloadIndex to LoadIndex at start-up. Ensures oldest events are processed first.
   // Clear Stats
   3: [XIC(InitialScan) ,XIC(ResetPulse) ][MOV(CurrentBufferIndex,UnloadIndex) MOV(0,EventsProcessed) ,MOV(0,LastElementIndex) MOV(0,LastStatus) MOV(0,LastValue) ];
   // Ensure UnloadIndex is within the EventBuffer bounds.
   4: GEQ(UnloadIndex,BufferSize)MOV(0,UnloadIndex);
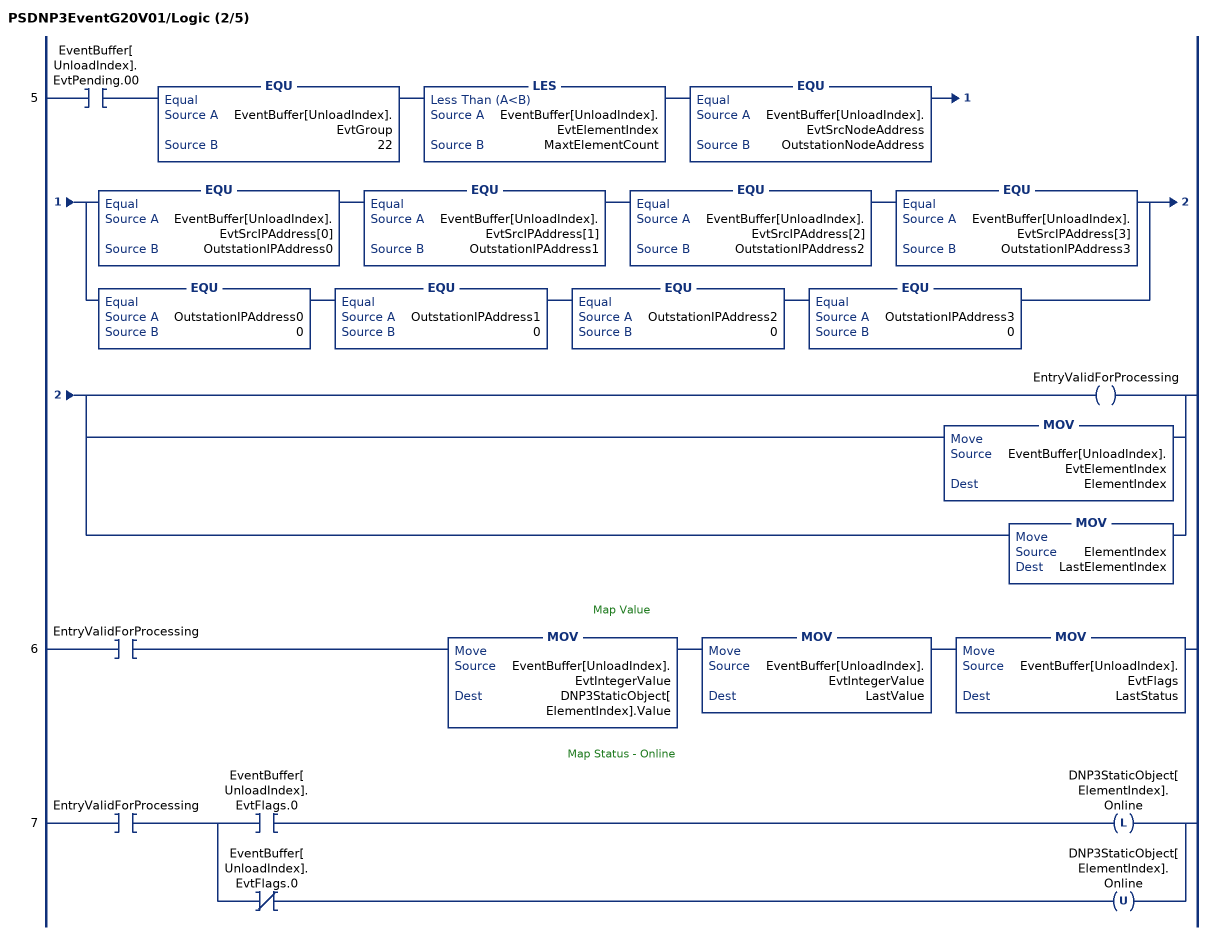
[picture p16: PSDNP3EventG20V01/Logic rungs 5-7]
   5: XIC(EventBuffer[UnloadIndex].EvtPending.00)EQU(EventBuffer[UnloadIndex].EvtGroup,22)LES(EventBuffer[UnloadIndex].EvtElementIndex,MaxtElementCount)EQU(EventBuffer[UnloadIndex].EvtSrcNodeAddress,OutstationNodeAddress)[EQU(EventBuffer[UnloadIndex].EvtSrcIPAddress[0],OutstationIPAddress0) EQU(EventBuffer[UnloadIndex].EvtSrcIPAddress[1],OutstationIPAddress1) EQU(EventBuffer[UnloadIndex].EvtSrcIPAddress[2],OutstationIPAddress2) EQU(EventBuffer[UnloadIndex].EvtSrcIPAddress[3],OutstationIPAddress3) ,EQU(OutstationIPAddress0,0) EQU(OutstationIPAddress1,0) EQU(OutstationIPAddress2,0) EQU(OutstationIPAddress3,0) ][OTE(EntryValidForProcessing) ,MOV(EventBuffer[UnloadIndex].EvtElementIndex,ElementIndex) ,MOV(ElementIndex,LastElementIndex) ];
   // Map Value
   6: XIC(EntryValidForProcessing)MOV(EventBuffer[UnloadIndex].EvtIntegerValue,DNP3StaticObject[ElementIndex].Value)MOV(EventBuffer[UnloadIndex].EvtIntegerValue,LastValue)MOV(EventBuffer[UnloadIndex].EvtFlags,LastStatus);
   // Map Status - Online
   7: XIC(EntryValidForProcessing)[XIC(EventBuffer[UnloadIndex].EvtFlags.0) OTL(DNP3StaticObject[ElementIndex].Online) ,XIO(EventBuffer[UnloadIndex].EvtFlags.0) OTU(DNP3StaticObject[ElementIndex].Online) ];
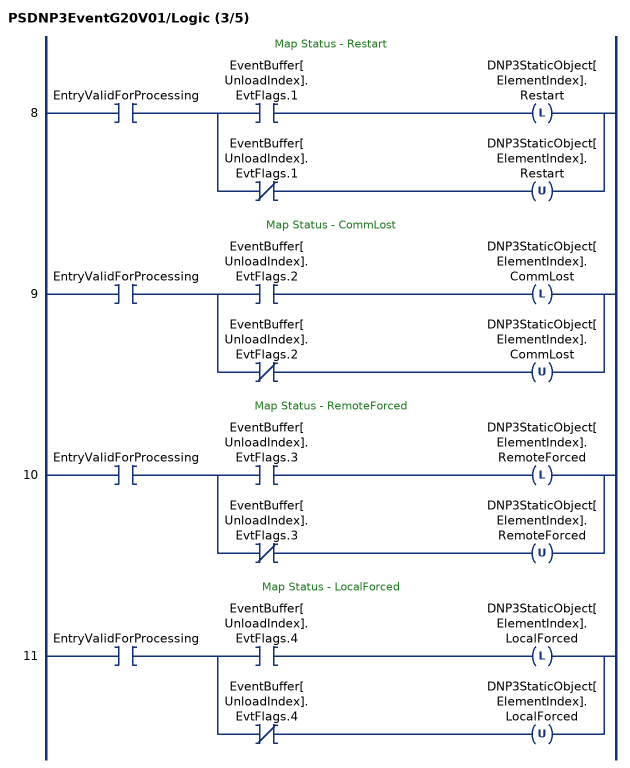
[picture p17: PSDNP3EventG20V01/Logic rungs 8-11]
   // Map Status - Restart
   8: XIC(EntryValidForProcessing)[XIC(EventBuffer[UnloadIndex].EvtFlags.1) OTL(DNP3StaticObject[ElementIndex].Restart) ,XIO(EventBuffer[UnloadIndex].EvtFlags.1) OTU(DNP3StaticObject[ElementIndex].Restart) ];
   // Map Status - CommLost
   9: XIC(EntryValidForProcessing)[XIC(EventBuffer[UnloadIndex].EvtFlags.2) OTL(DNP3StaticObject[ElementIndex].CommLost) ,XIO(EventBuffer[UnloadIndex].EvtFlags.2) OTU(DNP3StaticObject[ElementIndex].CommLost) ];
   // Map Status - RemoteForced
   10: XIC(EntryValidForProcessing)[XIC(EventBuffer[UnloadIndex].EvtFlags.3) OTL(DNP3StaticObject[ElementIndex].RemoteForced) ,XIO(EventBuffer[UnloadIndex].EvtFlags.3) OTU(DNP3StaticObject[ElementIndex].RemoteForced) ];
   // Map Status - LocalForced
   11: XIC(EntryValidForProcessing)[XIC(EventBuffer[UnloadIndex].EvtFlags.4) OTL(DNP3StaticObject[ElementIndex].LocalForced) ,XIO(EventBuffer[UnloadIndex].EvtFlags.4) OTU(DNP3StaticObject[ElementIndex].LocalForced) ];
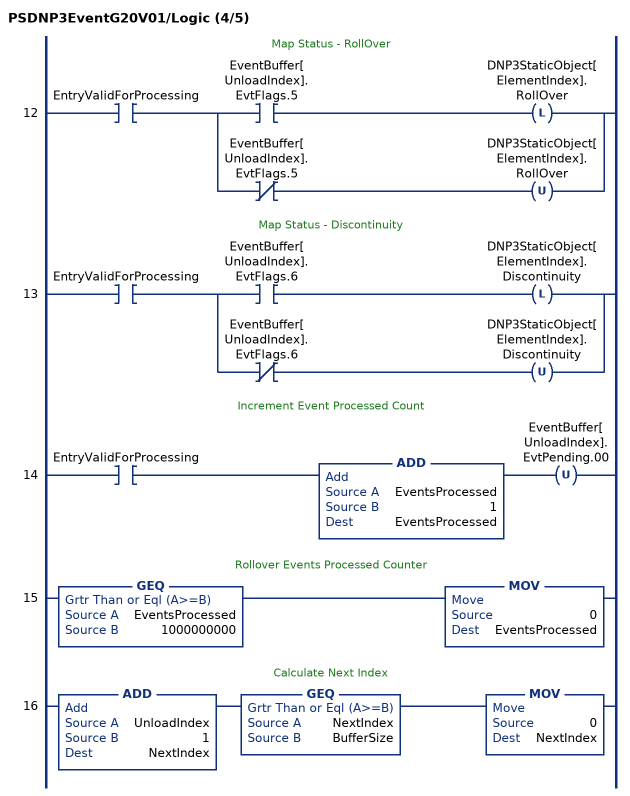
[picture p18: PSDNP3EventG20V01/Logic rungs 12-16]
   // Map Status - RollOver
   12: XIC(EntryValidForProcessing)[XIC(EventBuffer[UnloadIndex].EvtFlags.5) OTL(DNP3StaticObject[ElementIndex].RollOver) ,XIO(EventBuffer[UnloadIndex].EvtFlags.5) OTU(DNP3StaticObject[ElementIndex].RollOver) ];
   // Map Status - Discontinuity
   13: XIC(EntryValidForProcessing)[XIC(EventBuffer[UnloadIndex].EvtFlags.6) OTL(DNP3StaticObject[ElementIndex].Discontinuity) ,XIO(EventBuffer[UnloadIndex].EvtFlags.6) OTU(DNP3StaticObject[ElementIndex].Discontinuity) ];
   // Increment Event Processed Count
   14: XIC(EntryValidForProcessing)ADD(EventsProcessed,1,EventsProcessed)OTU(EventBuffer[UnloadIndex].EvtPending.00);
   // Rollover Events Processed Counter
   15: GEQ(EventsProcessed,1000000000)MOV(0,EventsProcessed);
   // Calculate Next Index
   16: ADD(UnloadIndex,1,NextIndex)GEQ(NextIndex,BufferSize)MOV(0,NextIndex);
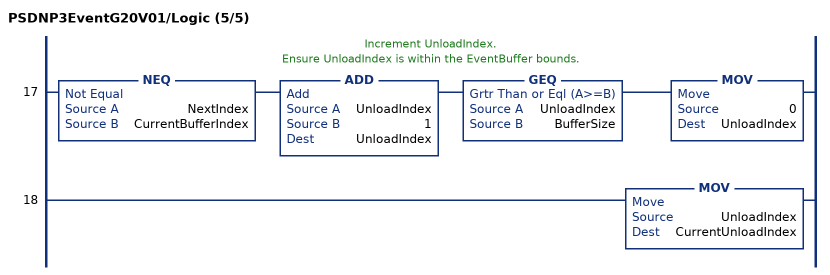
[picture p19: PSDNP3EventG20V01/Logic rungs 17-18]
   // Increment UnloadIndex.
   // Ensure UnloadIndex is within the EventBuffer bounds.
   17: NEQ(NextIndex,CurrentBufferIndex)ADD(UnloadIndex,1,UnloadIndex)GEQ(UnloadIndex,BufferSize)MOV(0,UnloadIndex);
   18: MOV(UnloadIndex,CurrentUnloadIndex);
END_ROUTINE
END_ADD_ON_INSTRUCTION
